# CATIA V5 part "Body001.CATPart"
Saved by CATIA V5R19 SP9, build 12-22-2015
Part number: Body001
Definition: design
Nomenclature: Body001
Source: Unknown
Bounding box of the stored display mesh (mm): x -59 to 59, y -3 to 0, z -17 to 17
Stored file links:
  Z:\charly_robot\Body001.CATPart
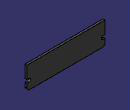
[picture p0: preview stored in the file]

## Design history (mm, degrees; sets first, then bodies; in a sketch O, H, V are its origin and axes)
AxisSystem1: origin (0, 0, 0), X (1, 0, 0), Y (0, 1, 0), Z (0, 0, 1)
Body1 "MANIFOLD_SOLID_BREP #5497" (main body)
  Solid1: solid without history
